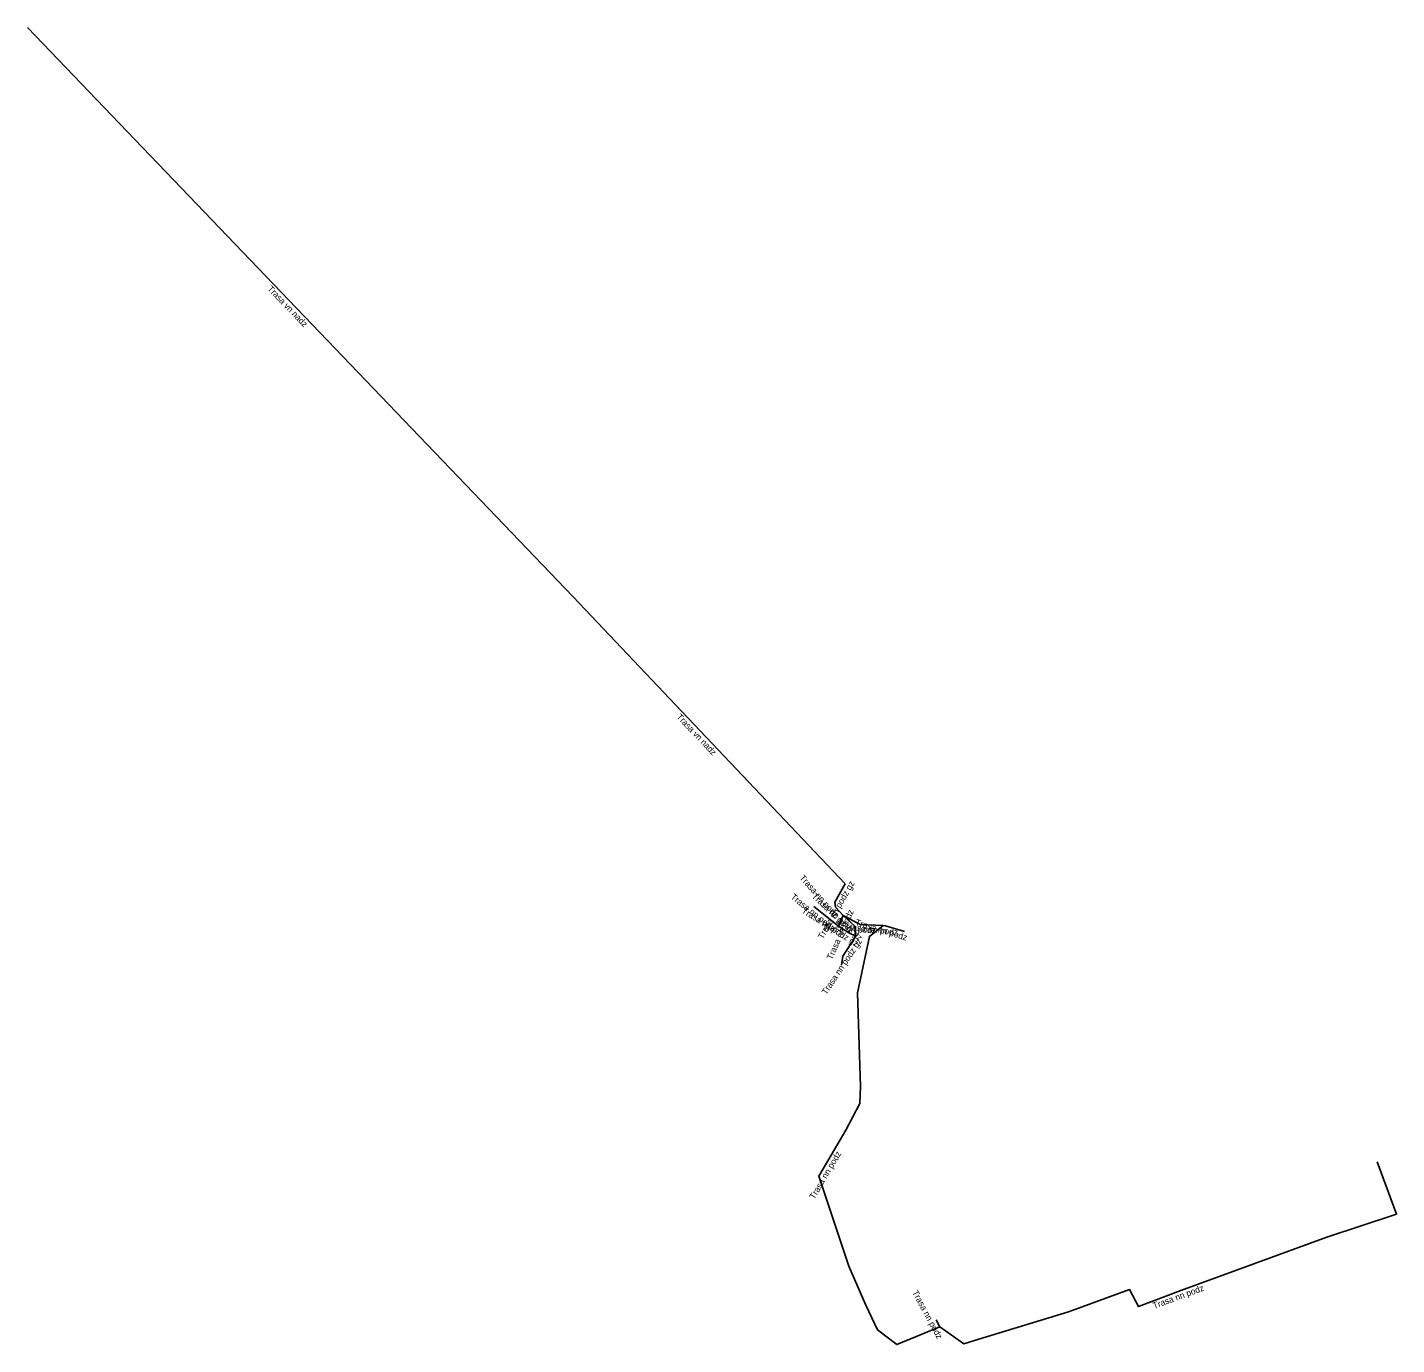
# Model space of a CAD drawing. Extents: x -677644 to -676951, y -1057278 to -1056718.
# Drawn here: x -677644.3 to -677535.5, y -1057278.1 to -1057173.4 of the extents above; entities that cross this region are included whole.
import ezdxf

# ---------------------------------------------------------------- set-up
doc = ezdxf.new("R2010")
doc.units = 0
for name, color, linetype in [('Popiskový text - Ostatní atributy Trasy', 7, 'Continuous'), ('Spojnice NN', 7, 'Continuous'), ('Spojnice VN', 7, 'Continuous')]:
    doc.layers.add(name, color=color, linetype=linetype)

msp = doc.modelspace()

# ---------------------------------------------------------------- linework, layer by layer
at = {"layer": 'Spojnice NN'}
for points in [[(-677580.14, -1057242.95), (-677579.32, -1057241.5)], [(-677579.85, -1057244.86), (-677581.8, -1057243.3)], [(-677579.47, -1057244.01), (-677580.07, -1057243.34), (-677580.14, -1057242.95)], [(-677576.28, -1057244.82), (-677577.39, -1057245.68), (-677578.32, -1057250.18), (-677578.1, -1057257.62), (-677578.14, -1057258.97), (-677579.26, -1057261.1), (-677581.4, -1057264.74), (-677579.02, -1057271.92), (-677577.68, -1057275.01), (-677576.74, -1057276.98), (-677575.21, -1057278.15), (-677571.79, -1057276.74)], [(-677579.47, -1057244.01), (-677579.85, -1057244.86)], [(-677579.85, -1057244.86), (-677579.02, -1057245.39), (-677578.46, -1057245.66)], [(-677578.46, -1057245.66), (-677578.55, -1057244.87), (-677579.47, -1057244.01)], [(-677579.47, -1057244.01), (-677578.12, -1057244.73), (-677576.28, -1057244.82)], [(-677576.28, -1057244.82), (-677576.1, -1057244.84)], [(-677576.1, -1057244.84), (-677574.6, -1057245.3)], [(-677579.6, -1057247.97), (-677579.51, -1057247.24), (-677578.46, -1057245.66)], [(-677537.01, -1057263.61), (-677535.47, -1057267.78), (-677541.02, -1057269.59), (-677552.62, -1057273.84), (-677555.99, -1057275.13), (-677556.71, -1057273.76), (-677561.56, -1057275.54), (-677568.69, -1057277.71), (-677569.89, -1057278.08), (-677571.79, -1057276.74)], [(-677571.79, -1057276.74), (-677572.09, -1057276.18)]]:
    msp.add_lwpolyline(points, dxfattribs=at)
at = {"layer": 'Spojnice VN'}
for points in [[(-677644.33, -1057173.37), (-677600.94, -1057218.68)], [(-677600.94, -1057218.68), (-677579.32, -1057241.5)]]:
    msp.add_lwpolyline(points, dxfattribs=at)

# ---------------------------------------------------------------- texts
at = {"layer": 'Popiskový text - Ostatní atributy Trasy'}
for s, rotation, p in [('Trasa vn nadz', 313.7639, (-677625.28, -1057194.2)), ('Trasa vn nadz', 313.4454, (-677592.76, -1057228.25)), ('Trasa nn podz gz', 311.6757, (-677582.98, -1057241.05)), ('Trasa nn podz gz', 60.5879, (-677581.08, -1057245.94)), ('Trasa nn podz', 321.3008, (-677583.69, -1057242.62)), ('Trasa nn podz gz', 317.0638, (-677582.01, -1057242.54)), ('Trasa nn podz gz', 327.5556, (-677582.81, -1057243.75)), ('Trasa nn podz', 65.9437, (-677580.35, -1057247.58)), ('Trasa nn podz', 357.1997, (-677581.14, -1057245.23)), ('Trasa nn podz', 353.6598, (-677579.39, -1057245.13)), ('Trasa nn podz', 342.951, (-677578.55, -1057244.77)), ('Trasa nn podz gz', 56.3937, (-677580.8, -1057250.36)), ('Trasa nn podz', 59.5482, (-677581.76, -1057266.63)), ('Trasa nn podz', 298.1786, (-677574, -1057273.99)), ('Trasa nn podz', 20.1218, (-677554.75, -1057275.31))]:
    msp.add_text(s, height=0.5, rotation=rotation, dxfattribs=at).set_placement(p)

doc.saveas('drawing.dxf')
